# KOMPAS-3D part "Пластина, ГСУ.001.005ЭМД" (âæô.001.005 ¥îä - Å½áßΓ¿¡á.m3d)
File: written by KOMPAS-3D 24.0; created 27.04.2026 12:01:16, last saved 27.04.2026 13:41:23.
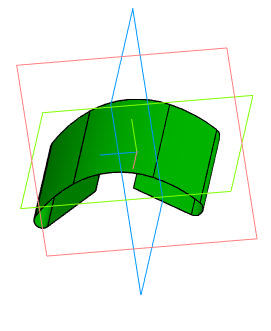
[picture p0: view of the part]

Document properties: Автор: USG_411; Полное имя файла: C:\Users\USG_411.STUD\Desktop\ГМ2704_411-23\Двигатель мясорубки\ГСУ.001.005 ЭМД - Пластина.m3d

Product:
- Part/product: Пластина  | designation ГСУ.001.005ЭМД
    Масса: 0.002575

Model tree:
1. Эскиз:1
2. Листовое тело:1
     Расстояние 1 = 38; Толщина листового тела = 0.1; Радиус сгиба = 38; Радиус сгиба = 1.9; Коэффициент = 0.4; Величина сгиба = 10; Радиус сгиба = 32.5232; Коэффициент = 0.4; Величина сгиба = 10; Радиус сгиба = 21.908; Коэффициент = 0.4; Величина сгиба = 10; Радиус сгиба = 32.5232; Коэффициент = 0.4; Величина сгиба = 10; Радиус сгиба = 1.9; Коэффициент = 0.4; Величина сгиба = 10

Expressions: 19/2; 36.3/2
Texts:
  ГСУ.001.005
  ГСУ.001.005 ЭМД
